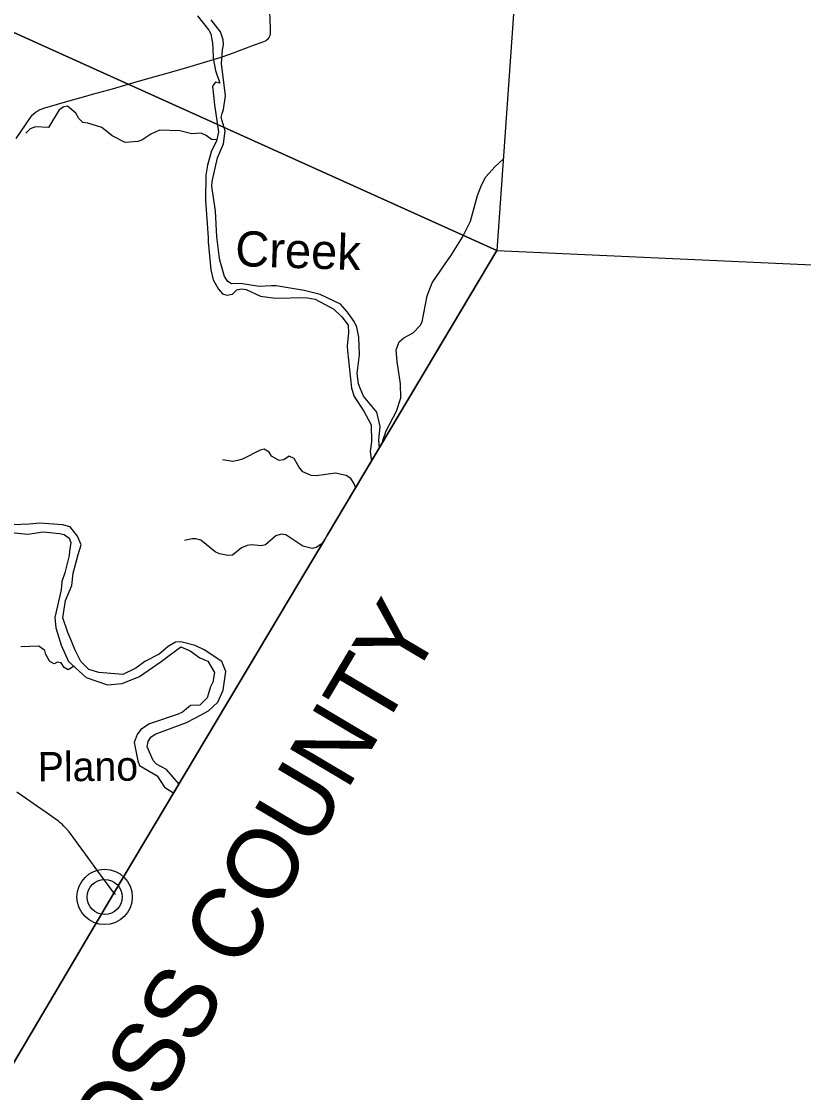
# Model space of a CAD drawing. Extents: x -51392 to 1635000, y 156707 to 696232.
# Drawn here: x 180722 to 191834, y 467379 to 482594 of the extents above; entities that cross this region are included whole.
import ezdxf

# ---------------------------------------------------------------- set-up
doc = ezdxf.new("R2010")
doc.units = 0
for name, color, linetype in [('GM_X_Adjacent_County', 7, 'Continuous'), ('GM_X_Adjacent_County_Text', 7, 'Continuous'), ('GM_X_County', 7, 'Continuous'), ('GM_X_County_Road', 7, 'Continuous'), ('GM_X_Major_River', 7, 'Continuous'), ('GM_X_Major_River_Text', 7, 'Continuous'), ('GM_X_Minor_River', 7, 'Continuous'), ('GM_X_Township', 7, 'Continuous'), ('GM_X_Unincorporated', 7, 'Continuous'), ('GM_X_Unincorporated_Text', 7, 'Continuous')]:
    doc.layers.add(name, color=color, linetype=linetype)

msp = doc.modelspace()

# ---------------------------------------------------------------- linework, layer by layer
at = {"layer": 'GM_X_Adjacent_County'}
for points in [[(192517, 562951), (192280, 559515), (192063, 555533), (191849, 551619), (191828, 551227), (191474, 544744), (191470, 544658), (190603, 531017), (189983, 519189), (189871, 517055), (189823, 516133), (189395, 507976), (188717, 497545), (188564, 495053), (188562, 495018), (188420, 492711), (187477, 479338), (192583, 479108), (200837, 478683), (211027, 478155)], [(177674, 462830), (180454, 467533), (182037, 470210), (184665, 474619), (185032, 475236), (185070, 475300), (187477, 479338), (192583, 479108), (200837, 478683), (211027, 478155)]]:
    msp.add_lwpolyline(points, dxfattribs=at)
at = {"layer": 'GM_X_County'}
msp.add_lwpolyline([(167692, 546175), (177006, 545575), (182001, 545258), (186228, 544990), (191470, 544658), (190603, 531017), (189983, 519189), (189871, 517055), (189823, 516133), (189395, 507976), (188717, 497545), (188564, 495053), (188562, 495018), (188420, 492711), (187477, 479338), (185070, 475300), (185032, 475236), (184665, 474619), (182037, 470210), (180454, 467533), (177674, 462830)], dxfattribs=at)
at = {"layer": 'GM_X_County_Road'}
for points in [[(182241, 481702), (182552, 481791), (182709, 481837), (183025, 481926), (183260, 481997), (183558, 482087), (183682, 482131), (184036, 482260), (184144, 482299), (184188, 482319), (184203, 482328), (184215, 482336), (184226, 482347), (184236, 482359), (184245, 482372), (184252, 482388), (184256, 482402), (184259, 482415), (184260, 482433), (184260, 482498), (184249, 482859)], [(180646, 480931), (180850, 481229), (180882, 481268), (180919, 481302), (180946, 481321), (180990, 481343), (181053, 481365), (181415, 481470), (181604, 481524), (181731, 481560), (182016, 481638), (182241, 481702)], [(182058, 470195), (182052, 470199), (182020, 470236), (181807, 470526), (181672, 470711), (181399, 471081), (181346, 471144), (181322, 471170), (181299, 471191), (181275, 471211), (181248, 471232), (181073, 471355), (180659, 471645)]]:
    msp.add_lwpolyline(points, dxfattribs=at)
at = {"layer": 'GM_X_Major_River'}
msp.add_line((185694, 476342), (185810, 476537), dxfattribs=at)
for points in [[(183223, 482674), (183385, 482471), (183411, 482419), (183439, 482287), (183441, 482205), (183447, 482073), (183479, 481896), (183539, 481718), (183479, 481732), (183435, 481676), (183465, 481409), (183521, 481027), (183493, 480892), (183422, 480756), (183364, 480550), (183344, 480412), (183338, 480053), (183374, 479518), (183374, 479462), (183412, 479063), (183447, 478925), (183521, 478792), (183577, 478726), (183641, 478704), (183721, 478718), (183781, 478782), (183851, 478796), (183917, 478786), (184119, 478690), (184329, 478663), (184759, 478673), (184897, 478647), (185163, 478506), (185273, 478398), (185363, 478281), (185369, 478175), (185349, 477983), (185355, 477917), (185411, 477384), (185449, 477267), (185589, 477059), (185689, 476866), (185698, 476620)], [(185810, 476537), (185802, 476646), (185817, 476840), (185771, 477045), (185581, 477271), (185535, 477386), (185511, 477448), (185491, 477592), (185523, 477856), (185517, 478109), (185489, 478253), (185449, 478331), (185353, 478466), (185257, 478576), (184965, 478715), (184739, 478771), (184342, 478840), (184277, 478838), (184101, 478828), (183833, 478872), (183707, 478868), (183653, 478900), (183606, 478969), (183540, 479203), (183534, 479271), (183500, 479532), (183480, 479900), (183426, 480255), (183430, 480321), (183510, 480656), (183593, 480854), (183615, 481040), (183559, 481227), (183573, 481287), (183595, 481343), (183621, 481539), (183565, 481998), (183581, 482189), (183595, 482261), (183589, 482333), (183549, 482445), (183417, 482618)], [(185698, 476620), (185676, 476484), (185694, 476342)]]:
    msp.add_lwpolyline(points, dxfattribs=at)
at = {"layer": 'GM_X_Minor_River'}
msp.add_line((182886, 471630), (182963, 471760), dxfattribs=at)
for points in [[(183499, 480911), (183425, 480916), (183349, 480975), (183277, 481005), (183145, 480995), (182971, 481039), (182685, 481048), (182563, 480994), (182432, 480908), (182376, 480888), (182194, 480876), (182010, 480968), (181865, 481088), (181665, 481151), (181597, 481157), (181537, 481215), (181495, 481293), (181379, 481390), (181327, 481380), (181259, 481338), (181106, 481085), (180922, 481096), (180848, 481070), (180786, 481008)], [(185855, 476608), (185856, 476640), (185903, 476780), (186053, 477060), (186113, 477249), (186109, 477445), (186059, 477764), (186045, 477930), (186089, 478042), (186155, 478100), (186287, 478172), (186389, 478274), (186417, 478326), (186488, 478697), (186556, 478881), (186784, 479210), (186822, 479266), (186990, 479528), (187102, 479756), (187200, 480123), (187260, 480267), (187319, 480387), (187453, 480531), (187568, 480637)], [(185472, 475970), (185444, 476035), (185404, 476099), (185338, 476143), (185184, 476176), (184908, 476138), (184840, 476142), (184720, 476198), (184662, 476266), (184598, 476387), (184528, 476419), (184450, 476365), (184386, 476359), (184276, 476419), (184244, 476475), (184170, 476517), (184112, 476505), (183862, 476377), (183794, 476357), (183726, 476342), (183580, 476366)], [(180529, 475341), (180815, 475311), (181031, 475345), (181265, 475320), (181331, 475304), (181403, 475256), (181425, 475192), (181407, 475068), (181399, 475008), (181341, 474761), (181295, 474637), (181287, 474521), (181195, 474128), (181211, 473978), (181289, 473735), (181393, 473504)], [(181566, 473504), (181487, 473665), (181409, 473849), (181381, 473914), (181309, 474124), (181351, 474370), (181437, 474583), (181459, 474755), (181529, 475023), (181571, 475160), (181517, 475280), (181417, 475416), (181305, 475444), (180983, 475467), (180831, 475453), (180599, 475441)], [(185004, 475183), (184912, 475122), (184852, 475108), (184718, 475138), (184478, 475301), (184412, 475311), (184338, 475289), (184192, 475157), (184129, 475143), (183995, 475159), (183929, 475151), (183849, 475117), (183723, 475011), (183657, 475007), (183535, 475031), (183475, 475061), (183271, 475226), (183201, 475242), (183149, 475244), (183041, 475220)], [(181127, 473503), (181070, 473603), (181054, 473657), (180972, 473718), (180712, 473708)], [(183570, 473504), (183319, 473667), (183193, 473729), (182985, 473782), (182913, 473776), (182805, 473716), (182681, 473608), (182477, 473503)], [(182706, 473504), (182987, 473711), (183119, 473655), (183259, 473553), (183373, 473505)], [(181470, 473434), (181386, 473383), (181328, 473417), (181288, 473481), (181236, 473491), (181186, 473471), (181127, 473503)], [(181393, 473504), (181643, 473276), (181943, 473172), (182155, 473191), (182401, 473288), (182706, 473504)], [(182477, 473503), (182349, 473408), (182161, 473317), (181823, 473348), (181678, 473388), (181566, 473504)], [(183373, 473505), (183467, 473346), (183444, 473209), (183408, 473141), (183363, 472986), (183259, 472883), (183123, 472877), (183011, 472784), (182949, 472756), (182542, 472616), (182418, 472538), (182366, 472467), (182323, 472353), (182374, 472092), (182402, 472024), (182653, 471878), (182754, 471718), (182886, 471630)], [(182963, 471760), (182785, 471969), (182642, 472045), (182594, 472097), (182507, 472289), (182525, 472365), (182559, 472426), (182623, 472472), (183066, 472634), (183196, 472703), (183381, 472802), (183513, 472922), (183588, 473093), (183625, 473362), (183570, 473504)]]:
    msp.add_lwpolyline(points, dxfattribs=at)
at = {"layer": 'GM_X_Township'}
for points in [[(189395, 507976), (188717, 497545), (188564, 495053), (188562, 495018), (188420, 492711), (187477, 479338), (182187, 481727), (175673, 484669), (172889, 485842), (172638, 486540), (172068, 488107), (171766, 488945), (171546, 489529), (171507, 489607), (171449, 489690), (171338, 489846), (171047, 490256), (170778, 490644), (168306, 492432)], [(166293, 488255), (170778, 490644), (171047, 490256), (171338, 489846), (171449, 489690), (171507, 489607), (171546, 489529), (171766, 488945), (172068, 488107), (172638, 486540), (172889, 485842), (175673, 484669), (182187, 481727), (187477, 479338), (185070, 475300), (185032, 475236), (184665, 474619), (182037, 470210), (180454, 467533), (177674, 462830)]]:
    msp.add_lwpolyline(points, dxfattribs=at)
at = {"layer": 'GM_X_Unincorporated'}
for radius in [393, 249]:
    msp.add_circle((181905, 470158), radius, dxfattribs=at)

# ---------------------------------------------------------------- texts
at = {"layer": 'GM_X_Adjacent_County_Text'}
msp.add_text('ROSS COUNTY', height=1000, rotation=59.3193, dxfattribs=at).set_placement((181704, 465519))
at = {"layer": 'GM_X_Major_River_Text'}
msp.add_text('Creek', height=500, rotation=358.086, dxfattribs=at).set_placement((183754, 479120))
at = {"layer": 'GM_X_Unincorporated_Text'}
msp.add_text('Plano', height=417, rotation=0.5386, dxfattribs=at).set_placement((180956, 471797))

doc.saveas('drawing.dxf')
